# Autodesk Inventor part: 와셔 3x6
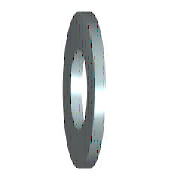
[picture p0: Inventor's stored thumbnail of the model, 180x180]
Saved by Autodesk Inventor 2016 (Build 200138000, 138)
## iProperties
IsCustomPart: 0
Created: 2012-02
Part Number: 와셔 3x6
Material: 강철, 연강
Description: 평면 와셔
Document SubType Name: Modeling
Standard: KS B 1326
Designer: mduedu
Standards Organization: KS
Language: ko-KR
Size Designation: 3x6
Categories: <MemberInstance><Categories><Category DisplayName="조임쇠" InternalName="e4da775c-781d-43d5-af7c-5136215cf5a6" Mnemonic="FSTN"><Category DisplayName="와셔" InternalN
Density: 7.86 g/cm^3
Mass: 0.0795112 g
Surface Area: 0.54915 cm^2
Volume: 0.0101159 cm^3
Appearance: 파란색 - 벽 페인트 - 광택
Author: mduedu
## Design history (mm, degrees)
sketch "스케치"
  geometry: C1 r 3 at (0, 0); C2 r 1.6 at (0, 0); 1 further point
  constraints: 2 centre point, 2 coincident
  dimensions: "d0" = 3.2 diameter of C2 (= SD1); "d1" = 6 diameter of C1 (= SD2)
extrude "본체" new body sketch "스케치" distance "d2" = 0.5 (= SD); taper "d3" = 0 deg
workaxis "Work Axis1"
workplane "Work Plane1"
body "Solid1"
other parameters: "SD1" = 3.2 [user parameter; used in 1 equation term], "SD2" = 6 [user parameter; used in 1 equation term], "SD" = 0.5 [user parameter; used in 1 equation term], "d4" = 0, "d5" = 0, "d6" = 0, "d7" = 0, "NND" = 3 [user parameter]
